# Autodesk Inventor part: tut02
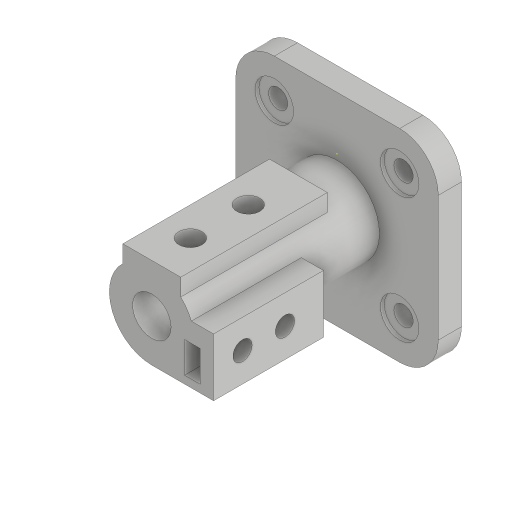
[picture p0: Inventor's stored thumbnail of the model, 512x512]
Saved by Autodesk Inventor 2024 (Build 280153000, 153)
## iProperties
Created: 2015-03
Part Number: tut02
Material: Generic
Document SubType Name: Modeling
Designer: Sandeep
Density: 1 g/cm^3
Appearance: Default
Author: Sandeep
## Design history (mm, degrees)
sketch "Sketch1"
  geometry: L1 (-32.5, -52.5)-(32.5, -52.5); L2 (52.5, -32.5)-(52.5, 32.5); L3 (32.5, 52.5)-(-32.5, 52.5); L4 (-52.5, 32.5)-(-52.5, -32.5); L5 (-52.5, -52.5)-(52.5, 52.5); L6 (52.5, -52.5)-(-52.5, 52.5); A1 r 20 centre (32.5, 32.5) between (52.5, 32.5) and (32.5, 52.5); A2 r 20 centre (32.5, -32.5) between (32.5, -52.5) and (52.5, -32.5); A3 r 20 centre (-32.5, -32.5) between (-52.5, -32.5) and (-32.5, -52.5); A4 r 20 centre (-32.5, 32.5) between (-32.5, 52.5) and (-52.5, 32.5); 1 further point
  constraints: 12 end point, 8 point on circle, 8 point on line, 8 tangent, 4 centre point, 2 equal radius, 2 midpoint, 2 parallel, 1 horizontal, 1 perpendicular
  dimensions: "d0" = 105 distance of L6.start L5.end; "d1" = 105 distance of L5.start L6.start; "d2" = 20 radius of A1; "d3" = 20 radius of A2
extrude "Extrusion1" new body sketch "Sketch1" distance "d4" = 12; taper "d5" = 0 deg
hole "Hole1" diameter "d8" = 10; stored, may be unused: countersink angle "d12" = 90 deg, drill point angle "d14" = 118 deg; dims "d9" = 6, "d10" = 20, "d11" = 2, "d13" = 8, "d15" = 10, "d16" = 10
hole "Hole2" diameter "d19" = 10; stored, may be unused: countersink angle "d23" = 90 deg, drill point angle "d25" = 118 deg; dims "d17" = 10, "d18" = 10, "d20" = 6, "d21" = 20, "d22" = 2, "d24" = 8
hole "Hole3" diameter "d28" = 10; stored, may be unused: countersink angle "d32" = 90 deg, drill point angle "d34" = 118 deg; dims "d26" = 10, "d27" = 10, "d29" = 6, "d30" = 20, "d31" = 2, "d33" = 8
hole "Hole4" diameter "d37" = 10; stored, may be unused: countersink angle "d41" = 90 deg, drill point angle "d43" = 118 deg; dims "d35" = 10, "d36" = 10, "d38" = 6, "d39" = 20, "d40" = 2, "d42" = 8
sketch "Sketch2"
  geometry: C1 r 22 at (0, 0); 1 further point
  constraints: 1 centre point, 1 coincident
  dimensions: "d44" = 44 diameter of C1
extrude "Extrusion2" join sketch "Sketch2" distance "d45" = 96; taper "d46" = 0 deg
sketch "Sketch3"
  geometry: L1 (-15, 16.093)-(-15, 25); L2 (15, 16.093)-(15, 25); L3 (-15, 25)-(15, 25); L4 (0, 0)-(20.619, 0); L5 (0, 6.043)-(0, 0); A1 r 22 centre (0, 0) between (15, 16.093) and (-15, 16.093); 1 further point
  constraints: 10 end point, 3 vertical, 2 horizontal, 2 point on circle, 1 centre point, 4 other
  dimensions: "d48" = 25 distance from line of point (0, 0) L3; "d49" = 30 distance of L1.end L2.end
extrude "Extrusion3" join sketch "Sketch3" distance "d51" = 76; taper "d52" = 0 deg
sketch "Sketch4"
  geometry: L1 (20.494, 8)-(32, 8); L2 (32, 8)-(32, -22); L3 (0, 0)-(37.067, 0); L4 (0, -22)-(32, -22); A1 r 22 centre (0, 0) between (20.494, 8) and (0, -22) reference; A2 r 22 centre (0, 0) between (0, -22) and (20.494, 8); 1 further point
  constraints: 8 end point, 5 point on circle, 2 horizontal, 2 perpendicular, 1 centre point, 1 concentric, 1 tangent
  dimensions: "d53" = 30 distance of L2.end L1.end; "d54" = 32 distance from line of L2 point (0, 0)
extrude "Extrusion4" join sketch "Sketch4" distance "d55" = 57; taper "d56" = 0 deg
sketch "Sketch5"
  geometry: L1 (17, -2)-(25, -2); L2 (25, -2)-(25, -18); L3 (25, -18)-(17, -18); L4 (17, -18)-(17, -2); 1 further point
  constraints: 8 end point, 2 parallel, 1 horizontal, 1 perpendicular
  dimensions: "d57" = 16 distance of L1.end L2.end; "d58" = 2 distance from line of point (0, 0) L1; "d59" = 25 distance from line of point (0, 0) L2; "d60" = 8 distance of L2.end L3.end
extrude "Extrusion5" cut sketch "Sketch5" distance "d61" = 50; taper "d62" = 0 deg
hole "Hole10" diameter "d113" = 10; stored, may be unused: countersink angle "d117" = 90 deg, drill point angle "d119" = 118 deg; dims "d111" = 15, "d112" = 15, "d114" = 6, "d115" = 4, "d116" = 2, "d118" = 96
hole "Hole11" diameter "d122" = 10; stored, may be unused: countersink angle "d126" = 90 deg, drill point angle "d128" = 118 deg; dims "d120" = 37, "d121" = 15, "d123" = 6, "d124" = 4, "d125" = 2, "d127" = 96
sketch "Sketch9"
  geometry: C1 r 10 at (0, 0); 1 further point
  constraints: 1 centre point, 1 coincident
  dimensions: "d129" = 20 diameter of C1
extrude "Extrusion7" cut sketch "Sketch9" distance "d130" = 96; taper "d131" = 0 deg
sketch "Sketch10"
  geometry: L1 (15, -0.369)-(15, 146.33); L2 (30, 0)-(30, 76) reference; L3 (0, 0)-(30, 0) reference; C1 r 6 at (15, 20); C2 r 6 at (15, 50); 1 further point
  constraints: 2 centre point, 2 end point, 2 point on line, 1 equal radius, 1 vertical
  dimensions: "d132" = 15 distance between parallel lines of L1 L2; "d133" = 12 diameter of C1; "d134" = 20 distance from line of C1.centre L3; "d135" = 30 distance of C2.centre C1.centre
extrude "Extrusion8" cut sketch "Sketch10" stored distance "d136" = 96; taper "d137" = 0 deg; dims "d17" = 10
body "Solid1"
sketch "Sketch6"
  geometry: 1 further point
sketch "Sketch8"
  geometry: 1 further point
